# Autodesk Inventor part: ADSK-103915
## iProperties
Shininess: 0.0
Created: 2000-10
Part Number: ADSK-103915
Document SubType Name: Modeling
Stock Number: ADSK-103915
Density: 1 g/cm^3
Density: 0.0
Volumn: 0.0
Area: 0.0
PropertySet Name: Model Information
Control State: 0
Master: False
Checked Out: False
Author: gao
